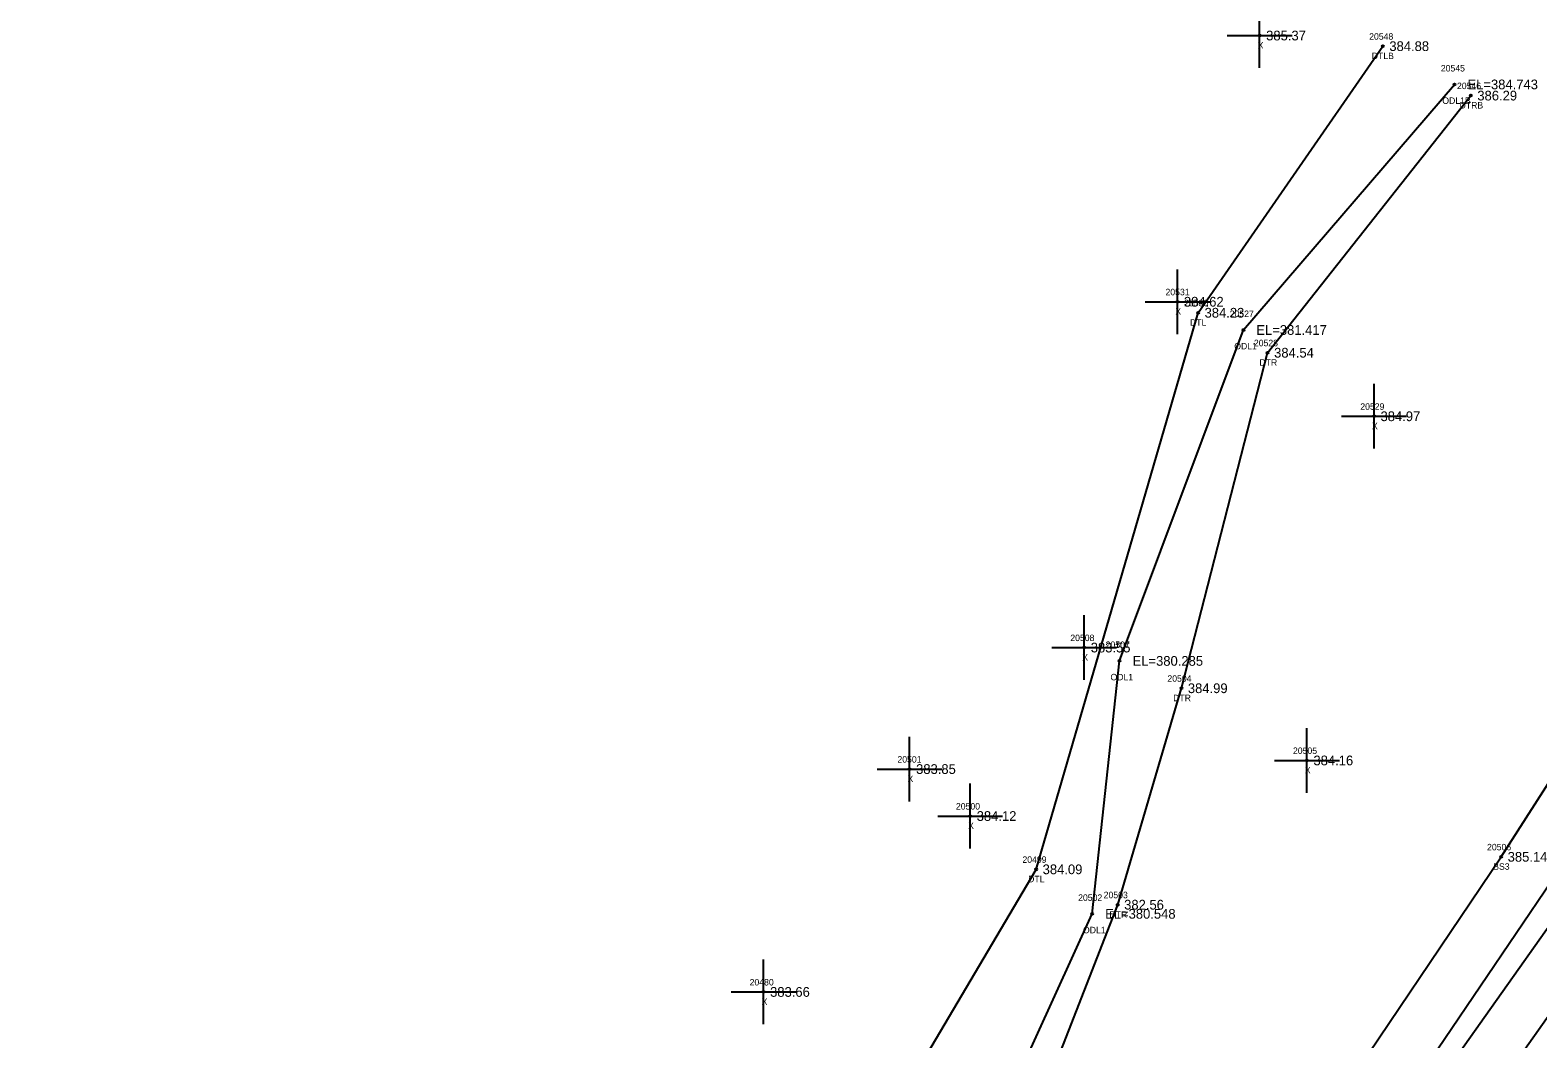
# Model space of a CAD drawing. Extents: x 2116373 to 2118139, y 979529 to 981026.
# Drawn here: x 2117652.3 to 2117884.9, y 980667.9 to 980823.7 of the extents above; entities that cross this region are included whole.
import ezdxf

# ---------------------------------------------------------------- set-up
doc = ezdxf.new("R2010")
doc.units = 0
for name, color, linetype in [('RD_DTM_BkLn1', 7, 'Continuous'), ('RD_DTM_BkLn2', 7, 'Continuous'), ('RD_DTM_BkLn_txCode', 7, 'Continuous'), ('RD_EX_H2O', 7, 'Continuous'), ('RD_EX_H2O_txCode', 7, 'Continuous'), ('RD_EX_Misc', 7, 'Continuous'), ('RD_EX_Misc_txCode', 7, 'Continuous'), ('RD_EX_Road', 7, 'Continuous'), ('RD_EX_TX_H2O_ELEV', 7, 'Continuous'), ('RD_EX_TX_Misc_ELEV', 7, 'Continuous'), ('RD_SMD_Locator', 7, 'Continuous')]:
    doc.layers.add(name, color=color, linetype=linetype)

msp = doc.modelspace()

# ---------------------------------------------------------------- linework, layer by layer
at = {"layer": 'RD_DTM_BkLn1'}
msp.add_lwpolyline([(2117394.63, 980185.41), (2117475.35, 980259.39), (2117549.63, 980326.58), (2117623.5, 980394.2), (2117697.55, 980461.75), (2117735.02, 980495.39), (2117805.43, 980566.78), (2117837.53, 980605.36), (2117867.93, 980645.06), (2117897.09, 980686.34), (2117923.66, 980727.51), (2117948.72, 980771.39), (2117971.22, 980818.34), (2117988.96, 980866.05), (2117991.42, 980873.14), (2118004.26, 980915.09), (2118016.82, 980963.49), (2118028.02, 981013.26)], dxfattribs=at)
at = {"layer": 'RD_DTM_BkLn2'}
for points in [[(2117493.39, 980317.39), (2117496.3, 980311.64), (2117501.39, 980308.35), (2117540.21, 980337.44), (2117614.76, 980403.8), (2117689.51, 980469.61), (2117729.91, 980504.53), (2117761.86, 980538.86), (2117795.32, 980575.41), (2117828.25, 980612.61), (2117859.59, 980651.69), (2117887.1, 980692.35), (2117913.78, 980733.2), (2117937.24, 980777.08), (2117959.23, 980820.82), (2117978.84, 980869.89), (2117994.26, 980920.18), (2118007.51, 980964.57), (2118017.18, 981016.23)], [(2117731.72, 980517.83), (2117742.59, 980526.71), (2117749.81, 980537.43), (2117757.84, 980543.55), (2117791.08, 980578.67), (2117820.63, 980617.19), (2117852.6, 980656.41), (2117879.28, 980696.02), (2117905.09, 980736.34), (2117929.71, 980780.7), (2117946.34, 980825.73), (2117956.18, 980836.51)]]:
    msp.add_lwpolyline(points, dxfattribs=at)
at = {"layer": 'RD_EX_H2O'}
for points in [[(2117721.89, 980511.88), (2117711.08, 980536.16), (2117721.34, 980544.67), (2117740.08, 980546.64), (2117756.52, 980607.75), (2117807.52, 980694.09), (2117832.51, 980780.02), (2117861.02, 980821.18)], [(2117660.7, 980455.28), (2117684.91, 980475.95), (2117725.61, 980509.35), (2117716.83, 980529.54), (2117716.58, 980532.55), (2117726.37, 980536.81), (2117746.69, 980542.31), (2117751.04, 980554.04), (2117763.83, 980600.87), (2117795.75, 980642.32), (2117816.16, 980687.22), (2117820.4, 980726.27), (2117839.5, 980777.36), (2117872.08, 980815.27)], [(2117731.72, 980517.83), (2117721.82, 980531.18), (2117732.04, 980532.84), (2117749.81, 980537.43), (2117752.02, 980549.86), (2117766.73, 980599.62), (2117799.8, 980636.48), (2117820.1, 980688.63), (2117829.93, 980722.05), (2117843.24, 980773.85), (2117874.6, 980813.55)]]:
    msp.add_lwpolyline(points, dxfattribs=at)
at = {"layer": 'RD_EX_Misc'}
for p, q in [((2117842.01, 980817.82), (2117842.01, 980827.82)), ((2117837.01, 980822.82), (2117847.01, 980822.82)), ((2117829.32, 980776.72), (2117829.32, 980786.72)), ((2117824.32, 980781.72), (2117834.32, 980781.72)), ((2117859.66, 980759.04), (2117859.66, 980769.04)), ((2117854.66, 980764.04), (2117864.66, 980764.04)), ((2117814.94, 980723.33), (2117814.94, 980733.33)), ((2117809.94, 980728.33), (2117819.94, 980728.33)), ((2117787.99, 980704.57), (2117787.99, 980714.57)), ((2117849.31, 980705.9), (2117849.31, 980715.9)), ((2117782.99, 980709.57), (2117792.99, 980709.57)), ((2117844.31, 980710.9), (2117854.31, 980710.9)), ((2117797.34, 980697.32), (2117797.34, 980707.32)), ((2117792.34, 980702.32), (2117802.34, 980702.32)), ((2117765.46, 980670.16), (2117765.46, 980680.16)), ((2117760.46, 980675.16), (2117770.46, 980675.16))]:
    msp.add_line(p, q, dxfattribs=at)
at = {"layer": 'RD_EX_Road'}
msp.add_lwpolyline([(2117394.63, 980185.41), (2117388.45, 980192.75), (2117469.76, 980266.25), (2117487.02, 980282.1), (2117515.02, 980307.24), (2117543.53, 980333.04), (2117617.72, 980400.8), (2117691.88, 980468.07), (2117729.57, 980501.96), (2117798.93, 980572.83), (2117831.02, 980611), (2117861.69, 980650.07), (2117890.37, 980690.61), (2117916.67, 980731.93), (2117941.38, 980774.84), (2117963.75, 980821.95), (2117981.56, 980869.78), (2117996.2, 980917.73), (2118008.9, 980966.42), (2118019.55, 981015.46)], dxfattribs=at)
at = {"layer": 'RD_SMD_Locator'}
for centre in [(2117842.01, 980822.82), (2117861.02, 980821.18), (2117872.08, 980815.27), (2117874.6, 980813.55), (2117829.32, 980781.72), (2117832.51, 980780.02), (2117839.5, 980777.36), (2117843.24, 980773.85), (2117859.66, 980764.04), (2117814.94, 980728.33), (2117820.4, 980726.27), (2117829.93, 980722.05), (2117787.99, 980709.57), (2117849.31, 980710.9), (2117797.34, 980702.32), (2117879.28, 980696.02), (2117807.52, 980694.09), (2117820.1, 980688.63), (2117816.16, 980687.22), (2117765.46, 980675.16)]:
    msp.add_circle(centre, 0.15, dxfattribs=at)

# ---------------------------------------------------------------- texts
at = {"layer": 'RD_DTM_BkLn_txCode'}
for s, p in [('20506', (2117877.1, 980697.02)), ('BS3', (2117878.05, 980694.02))]:
    msp.add_text(s, height=1, dxfattribs=at).set_placement(p)
at = {"layer": 'RD_EX_H2O_txCode'}
for s, p in [('20548', (2117858.91, 980822.18)), ('DTLB', (2117859.31, 980819.18)), ('20545', (2117869.97, 980817.27)), ('20546', (2117872.46, 980814.55)), ('ODL1B', (2117870.2, 980812.27)), ('DTRB', (2117872.86, 980811.55)), ('20530', (2117830.35, 980781.02)), ('20527', (2117837.39, 980779.36)), ('DTL', (2117831.26, 980778.02)), ('ODL1', (2117838.09, 980774.36)), ('20528', (2117841.12, 980774.85)), ('DTR', (2117841.97, 980771.85)), ('20507', (2117818.24, 980728.27)), ('ODL1', (2117818.99, 980723.27)), ('20504', (2117827.77, 980723.05)), ('DTR', (2117828.66, 980720.05)), ('20499', (2117805.4, 980695.09)), ('DTL', (2117806.28, 980692.09)), ('20502', (2117814, 980689.22)), ('20503', (2117817.94, 980689.63)), ('DTR', (2117818.83, 980686.63)), ('ODL1', (2117814.75, 980684.22))]:
    msp.add_text(s, height=1, dxfattribs=at).set_placement(p)
at = {"layer": 'RD_EX_Misc_txCode'}
for s, p in [('X', (2117841.7, 980820.82)), ('20531', (2117827.48, 980782.72)), ('X', (2117829, 980779.72)), ('20529', (2117857.54, 980765.04)), ('X', (2117859.34, 980762.04)), ('20508', (2117812.79, 980729.33)), ('X', (2117814.63, 980726.33)), ('20505', (2117847.15, 980711.9)), ('20501', (2117786.11, 980710.57)), ('X', (2117848.99, 980708.9)), ('X', (2117787.67, 980707.57)), ('20500', (2117795.14, 980703.32)), ('X', (2117797.02, 980700.32)), ('20480', (2117763.3, 980676.16)), ('X', (2117765.15, 980673.16))]:
    msp.add_text(s, height=1, dxfattribs=at).set_placement(p)
at = {"layer": 'RD_EX_TX_H2O_ELEV'}
for s, p in [('384.88', (2117862.02, 980820.43)), ('EL=384.743', (2117874.08, 980814.52)), ('386.29', (2117875.6, 980812.8)), ('384.23', (2117833.51, 980779.27)), ('EL=381.417', (2117841.5, 980776.61)), ('384.54', (2117844.24, 980773.1)), ('EL=380.285', (2117822.4, 980725.52)), ('384.99', (2117830.93, 980721.3)), ('384.09', (2117808.52, 980693.34)), ('382.56', (2117821.1, 980687.88)), ('EL=380.548', (2117818.16, 980686.47))]:
    msp.add_text(s, height=1.5, dxfattribs=at).set_placement(p)
at = {"layer": 'RD_EX_TX_Misc_ELEV'}
for s, p in [('385.37', (2117843.01, 980822.07)), ('384.62', (2117830.32, 980780.97)), ('384.97', (2117860.66, 980763.29)), ('383.55', (2117815.94, 980727.58)), ('383.85', (2117788.99, 980708.82)), ('384.16', (2117850.31, 980710.15)), ('384.12', (2117798.34, 980701.57)), ('385.14', (2117880.28, 980695.27)), ('383.66', (2117766.46, 980674.41))]:
    msp.add_text(s, height=1.5, dxfattribs=at).set_placement(p)

doc.saveas('drawing.dxf')
